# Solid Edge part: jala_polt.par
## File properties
Author: Mac
Template: Normal.par
Last saved by: Mac
Revision: 4
Application: Solid Edge
Material: Stainless steel
Face Style: Steel
Fill Style: ANSI32(Steel)
Virtual Style: Stainless steel
Coef. of Thermal Exp: 1.6e-05
Thermal Conductivity: 17.0
Specific Heat: 502.0
Modulus of Elasticity: 193053196000.0
Poission's Ratio: 0.29
Yield Stress: 310264065.0
Ultimate Stress: 641212401.0
Elongation: 0.0
Density: 7750,000 kg/m^3
Accuracy: 0,990
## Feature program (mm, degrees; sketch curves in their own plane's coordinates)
sketch for "unnamed Protrusion 1" plane through (0, 0, 0) normal (0, 0, 1) x-axis (1, 0, 0)
  circle centre (0, 0) radius 0.3
extrude "unnamed Protrusion 1" add finite 6.28 along +normal
sketch for "ExtrudedProtrusion_2" plane through (0, 0, 6.28) normal (0, 0, 1) x-axis (1, 0, 0)
  circle centre (0, 0) radius 0.5
extrude "ExtrudedProtrusion_2" add finite 0.2 along +normal
sketch for "unnamed Cutout 1" plane through (0, 0, 0) normal (1, 0, 0) x-axis (0, 1, 0)
  circle centre (0.0012, 0.9) radius 0.055
extrude "unnamed Cutout 1" cut to key point symmetric
fillet "Round_1" radius 0.05
sketch for "ExtrudedProtrusion_3" #1 plane through (0, 0, 0) normal (1, 0, 0) x-axis (0, 1, 0)
  circle centre (0, 6.78) radius 0.0702
sketch for "ExtrudedProtrusion_3" #2 plane through (0, 0, 0) normal (1, 0, 0) x-axis (0, 1, 0)
  line (-0.2134, 6.48) -> (0.2135, 6.48)
  line (0.1242, 6.8133) -> (0.2135, 6.48)
  line (-0.1246, 6.8115) -> (-0.2134, 6.48)
extrude "ExtrudedProtrusion_3" add finite 0.14 symmetric
fillet "Round_4" radius 0.05
chamfer "Chamfer_4" setback 0.02
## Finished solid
Body 1: solid body, 22 faces, 38 edges, 16 vertices.
  Faces by surface: cylinder 9, plane 7, torus 4, spline 2
  Edges by curve: circle 16, line 14, curve on surface 4, ellipse 4
Bounding box of the edges (mm; curved faces can reach further): 1.000 x 1.000 x 6.909, from (-0.5, -0.5, 0) to (0.5, 0.5, 6.9085).
Cylindrical faces by radius (mm): R0.05 x4, R0.055 x1, R0.0702 x1, R0.1285 x1, R0.3 x1, R0.5 x1
Toroidal faces (ring radius, tube radius in mm): R0.0785 r0.05 x2, R0.25 r0.05 x1, R0.45 r0.05 x1
Planar faces by outward normal: +x 1, +z 1, -x 1, -z 2, oblique 2
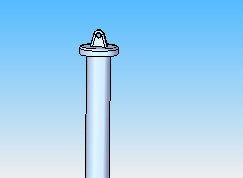
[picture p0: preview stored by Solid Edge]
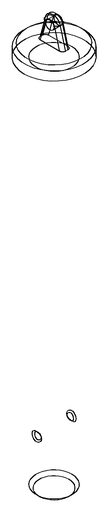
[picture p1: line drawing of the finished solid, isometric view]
